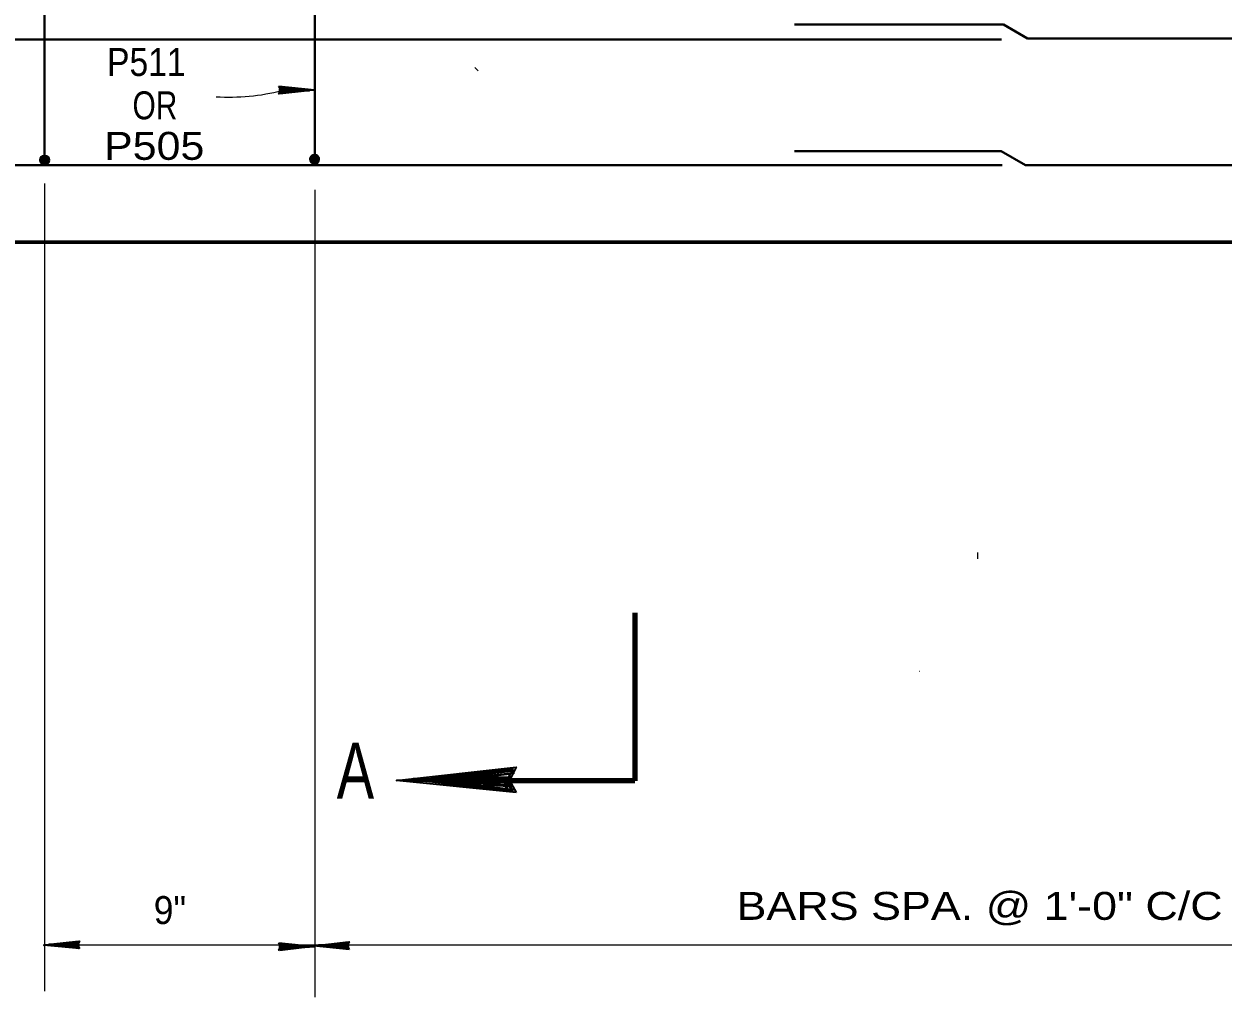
# Model space of a CAD drawing. Extents: x 6.34 to 9.53, y -1.46 to 0.53.
# Drawn here: x 6.7323 to 7.0899, y -1.0312 to -0.7412 of the extents above; entities that cross this region are included whole.
import ezdxf

# ---------------------------------------------------------------- set-up
doc = ezdxf.new("R2010")
doc.units = 0
doc.header["$LTSCALE"] = 0.0033
doc.layers.add('1', color=7, linetype='Continuous', lineweight=40)

msp = doc.modelspace()

# ---------------------------------------------------------------- linework, layer by layer
at = {"layer": '1'}
for p, q in [((6.738417, -0.6685), (6.738417, -0.780333)), ((6.819083, -0.667833), (6.819083, -0.780833)), ((6.737833, -0.780583), (6.7375, -0.782583)), ((6.737917, -0.780667), (6.737583, -0.782583)), ((6.738, -0.780667), (6.737667, -0.782583)), ((6.739167, -0.782), (6.737667, -0.781833)), ((6.739167, -0.782167), (6.737667, -0.782)), ((6.739167, -0.78225), (6.737667, -0.782167)), ((6.739167, -0.78225), (6.737667, -0.782167)), ((6.739167, -0.782333), (6.737667, -0.78225)), ((6.739167, -0.782417), (6.737667, -0.782333)), ((6.739167, -0.7825), (6.737667, -0.782417)), ((6.739167, -0.782583), (6.737667, -0.7825)), ((6.739167, -0.782667), (6.737667, -0.782583)), ((6.739167, -0.78275), (6.737667, -0.782667)), ((6.739167, -0.782917), (6.737667, -0.782833)), ((6.738083, -0.780667), (6.73775, -0.782667)), ((6.73925, -0.780833), (6.73775, -0.78075)), ((6.73925, -0.780917), (6.73775, -0.780833)), ((6.73925, -0.781), (6.73775, -0.780917)), ((6.73925, -0.781083), (6.73775, -0.781)), ((6.73925, -0.781167), (6.73775, -0.781083)), ((6.73925, -0.781333), (6.73775, -0.78125)), ((6.73925, -0.781417), (6.73775, -0.781333)), ((6.73925, -0.7815), (6.73775, -0.781417)), ((6.73925, -0.781583), (6.73775, -0.7815)), ((6.73925, -0.781667), (6.73775, -0.781583)), ((6.73925, -0.78175), (6.73775, -0.781667)), ((6.73925, -0.781833), (6.73775, -0.78175)), ((6.738333, -0.780667), (6.737917, -0.782667)), ((6.7385, -0.78075), (6.738083, -0.782667)), ((6.738583, -0.78075), (6.738167, -0.782667)), ((6.738667, -0.78075), (6.73825, -0.78275)), ((6.73875, -0.78075), (6.738417, -0.78275)), ((6.738833, -0.780833), (6.7385, -0.78275)), ((6.739, -0.780833), (6.738583, -0.782833)), ((6.739083, -0.780833), (6.738667, -0.782833)), ((6.739167, -0.780833), (6.738833, -0.782833)), ((6.73925, -0.780833), (6.738917, -0.782833)), ((6.739417, -0.780917), (6.739083, -0.782833)), ((6.818333, -0.780333), (6.818, -0.782333)), ((6.818417, -0.780417), (6.818083, -0.782333)), ((6.8185, -0.780417), (6.818167, -0.782333)), ((6.819667, -0.78175), (6.818167, -0.781583)), ((6.819667, -0.781917), (6.818167, -0.78175)), ((6.819667, -0.782), (6.818167, -0.781917)), ((6.819667, -0.782), (6.818167, -0.781917)), ((6.819667, -0.782083), (6.818167, -0.782)), ((6.819667, -0.782167), (6.818167, -0.782083)), ((6.819667, -0.78225), (6.818167, -0.782167)), ((6.819667, -0.782333), (6.818167, -0.78225)), ((6.819667, -0.782417), (6.818167, -0.782333)), ((6.819667, -0.7825), (6.818167, -0.782417)), ((6.819667, -0.782667), (6.818167, -0.782583)), ((6.818583, -0.780417), (6.81825, -0.782417)), ((6.81975, -0.780583), (6.81825, -0.7805)), ((6.81975, -0.780667), (6.81825, -0.780583)), ((6.81975, -0.78075), (6.81825, -0.780667)), ((6.81975, -0.780833), (6.81825, -0.78075)), ((6.81975, -0.780917), (6.81825, -0.780833)), ((6.81975, -0.781083), (6.81825, -0.781)), ((6.81975, -0.781167), (6.81825, -0.781083)), ((6.81975, -0.78125), (6.81825, -0.781167)), ((6.81975, -0.781333), (6.81825, -0.78125)), ((6.81975, -0.781417), (6.81825, -0.781333)), ((6.81975, -0.7815), (6.81825, -0.781417)), ((6.81975, -0.781583), (6.81825, -0.7815)), ((6.818833, -0.780417), (6.818417, -0.782417)), ((6.819, -0.7805), (6.818583, -0.782417)), ((6.819083, -0.7805), (6.818667, -0.782417)), ((6.819167, -0.7805), (6.81875, -0.7825)), ((6.81925, -0.7805), (6.818917, -0.7825)), ((6.819333, -0.780583), (6.819, -0.7825)), ((6.8195, -0.780583), (6.819083, -0.782583)), ((6.819583, -0.780583), (6.819167, -0.782583)), ((6.819667, -0.780583), (6.819333, -0.782583)), ((6.81975, -0.780583), (6.819417, -0.782583)), ((6.819917, -0.780667), (6.819583, -0.782583))]:
    msp.add_line(p, q, dxfattribs=at)
at = {"layer": '1', "lineweight": 25}
for p, q in [((6.86675, -0.754167), (6.86775, -0.755167)), ((6.999333, -0.934083), (6.999417, -0.934083)), ((6.999333, -0.934083), (6.999417, -0.934083))]:
    msp.add_line(p, q, dxfattribs=at)
at = {"layer": '1', "lineweight": 35}
for p, q in [((6.808333, -0.760833), (6.818917, -0.760833)), ((6.8085, -0.7615), (6.815833, -0.76075)), ((6.808583, -0.759833), (6.816417, -0.76075)), ((6.808583, -0.759833), (6.816417, -0.76075)), ((6.808583, -0.759917), (6.816417, -0.76075)), ((6.808583, -0.76), (6.816417, -0.760833)), ((6.808583, -0.76), (6.816417, -0.761)), ((6.808583, -0.761667), (6.815917, -0.760833)), ((6.808583, -0.76175), (6.815917, -0.761)), ((6.808583, -0.761917), (6.815917, -0.761083)), ((6.878333, -0.963), (6.853583, -0.96575)), ((6.878333, -0.9635), (6.853583, -0.966167)), ((6.878333, -0.963917), (6.853583, -0.96675)), ((6.878583, -0.9645), (6.853667, -0.966917)), ((6.879083, -0.96675), (6.843417, -0.96675)), ((6.878333, -0.9695), (6.85175, -0.966167)), ((6.878333, -0.9695), (6.85175, -0.96675)), ((6.878333, -0.970167), (6.85175, -0.966917)), ((6.878333, -0.970167), (6.85175, -0.966917)), ((6.878333, -0.96975), (6.85175, -0.966917)), ((6.748583, -1.016583), (6.74075, -1.015583)), ((6.748583, -1.014667), (6.74125, -1.0155)), ((6.748583, -1.014833), (6.74125, -1.015583)), ((6.748583, -1.014917), (6.74125, -1.01575)), ((6.748667, -1.015083), (6.741333, -1.015833)), ((6.808583, -1.015167), (6.816417, -1.016083)), ((6.808583, -1.015167), (6.816417, -1.016083)), ((6.808583, -1.01525), (6.816417, -1.016083)), ((6.808583, -1.015333), (6.816417, -1.016167)), ((6.808583, -1.015333), (6.816417, -1.016333)), ((6.829, -1.014917), (6.821667, -1.01575)), ((6.829, -1.015083), (6.821667, -1.015833)), ((6.829, -1.015167), (6.821667, -1.016)), ((6.829083, -1.015333), (6.82175, -1.016083)), ((6.748833, -1.01575), (6.73825, -1.01575)), ((6.748583, -1.016583), (6.74075, -1.01575)), ((6.748583, -1.01675), (6.74075, -1.015833)), ((6.748583, -1.01675), (6.74075, -1.015833)), ((6.748583, -1.016667), (6.74075, -1.015833)), ((6.808333, -1.016167), (6.818917, -1.016167)), ((6.8085, -1.016833), (6.815833, -1.016083)), ((6.808583, -1.017), (6.815917, -1.016167)), ((6.808583, -1.017083), (6.815917, -1.016333)), ((6.808583, -1.01725), (6.815917, -1.016417)), ((6.82925, -1.016), (6.818667, -1.016)), ((6.829, -1.016833), (6.821167, -1.015833)), ((6.829, -1.016833), (6.821167, -1.016)), ((6.829, -1.017), (6.821167, -1.016083)), ((6.829, -1.017), (6.821167, -1.016083)), ((6.829, -1.016917), (6.821167, -1.016083))]:
    msp.add_line(p, q, dxfattribs=at)
at = {"layer": '1', "lineweight": 13}
for p, q in [((6.738417, -0.780333), (6.738417, -0.780417)), ((6.738417, -0.78875), (6.738417, -1.0295)), ((6.819083, -0.790583), (6.819083, -1.03125)), ((7.01675, -0.89875), (7.01675, -0.900667)), ((7.01675, -0.89875), (7.01675, -0.900667)), ((7.290917, -1.01575), (6.739167, -1.01575))]:
    msp.add_line(p, q, dxfattribs=at)
at = {"layer": '1', "lineweight": 60}
msp.add_line((7.385583, -0.80625), (6.635583, -0.80625), dxfattribs=at)
at = {"layer": '1', "lineweight": 90}
for p, q in [((6.9145, -0.91675), (6.9145, -0.966833)), ((6.9145, -0.966833), (6.872833, -0.966833))]:
    msp.add_line(p, q, dxfattribs=at)
at = {"layer": '1'}
for points in [[(6.962083, -0.741333), (7.024417, -0.741333), (7.031667, -0.7455), (7.367083, -0.7455)], [(6.654, -0.745833), (6.962083, -0.745833), (7.023833, -0.745833)], [(6.962167, -0.779083), (7.02375, -0.779083), (7.031, -0.78325), (7.367917, -0.78325)], [(6.738417, -0.780417), (6.73875, -0.783), (6.73925, -0.780667), (6.738167, -0.783), (6.73775, -0.780583), (6.737417, -0.782583), (6.7395, -0.782583), (6.737167, -0.781667), (6.73975, -0.781917), (6.737417, -0.780917), (6.73975, -0.78125), (6.737167, -0.782083), (6.738917, -0.7805), (6.739083, -0.782917), (6.73725, -0.78125), (6.739667, -0.782333), (6.73925, -0.780667), (6.73775, -0.780583), (6.737167, -0.781667), (6.737417, -0.782583), (6.738167, -0.783), (6.739083, -0.782917), (6.739667, -0.782333), (6.738583, -0.781667), (6.737667, -0.782833), (6.737417, -0.780917), (6.738583, -0.781667), (6.739083, -0.780583), (6.73975, -0.781583), (6.738667, -0.781667), (6.737417, -0.7825), (6.738667, -0.7805), (6.739, -0.781833), (6.7395, -0.782583)], [(6.818917, -0.780167), (6.81925, -0.78275), (6.81975, -0.780417), (6.818667, -0.78275), (6.81825, -0.780333), (6.817917, -0.782333), (6.82, -0.782333), (6.817667, -0.781417), (6.82025, -0.781667), (6.817917, -0.780667), (6.82025, -0.781), (6.817667, -0.781833), (6.819417, -0.78025), (6.819583, -0.782667), (6.81775, -0.781), (6.820167, -0.782083), (6.81975, -0.780417), (6.81825, -0.780333), (6.817667, -0.781417), (6.817917, -0.782333), (6.818667, -0.78275), (6.819583, -0.782667), (6.820167, -0.782083), (6.819083, -0.781417), (6.818167, -0.782583), (6.817917, -0.780667), (6.819083, -0.781417), (6.819583, -0.780333), (6.82025, -0.781333), (6.819167, -0.781417), (6.817917, -0.78225), (6.819167, -0.78025), (6.8195, -0.781583), (6.82, -0.782333)], [(6.653167, -0.78325), (6.962167, -0.78325), (7.024083, -0.78325)]]:
    msp.add_lwpolyline(points, dxfattribs=at)
at = {"layer": '1', "lineweight": 35}
for points in [[(6.808333, -0.75975), (6.818917, -0.760833), (6.808333, -0.762), (6.808917, -0.760833)], [(6.809083, -0.76075), (6.81375, -0.760667), (6.81375, -0.76075), (6.812833, -0.76075), (6.809083, -0.760667), (6.812083, -0.760583), (6.808917, -0.7605), (6.811167, -0.760417), (6.808917, -0.760333), (6.812417, -0.760583), (6.817083, -0.76075), (6.816167, -0.761), (6.817417, -0.761), (6.809083, -0.761), (6.8115, -0.761167), (6.808917, -0.761167), (6.81425, -0.76075), (6.808917, -0.761417)], [(6.879083, -0.97025), (6.843417, -0.96675), (6.879083, -0.96275), (6.877167, -0.96675)], [(6.876667, -0.966917), (6.860833, -0.96725), (6.860833, -0.966917), (6.863833, -0.966917), (6.876667, -0.96725), (6.866417, -0.9675), (6.877167, -0.967917), (6.869417, -0.968), (6.877167, -0.968417), (6.865333, -0.9675), (6.8495, -0.966917), (6.852583, -0.966167), (6.848417, -0.966167), (6.876667, -0.966167), (6.868333, -0.965667), (6.877167, -0.965667), (6.859167, -0.966917), (6.877167, -0.964667)], [(6.748833, -1.016833), (6.73825, -1.01575), (6.748833, -1.014583), (6.74825, -1.01575)], [(6.748083, -1.015833), (6.743417, -1.015917), (6.743417, -1.015833), (6.744333, -1.015833), (6.748083, -1.015917), (6.745083, -1.016), (6.74825, -1.016083), (6.746, -1.016167), (6.74825, -1.01625), (6.74475, -1.016), (6.740083, -1.015833), (6.741, -1.015583), (6.73975, -1.015583), (6.748083, -1.015583), (6.745667, -1.015417), (6.74825, -1.015417), (6.742917, -1.015833), (6.74825, -1.015167)], [(6.808333, -1.015083), (6.818917, -1.016167), (6.808333, -1.017333), (6.808917, -1.016167)], [(6.809083, -1.016083), (6.81375, -1.016), (6.81375, -1.016083), (6.812833, -1.016083), (6.809083, -1.016), (6.812083, -1.015917), (6.808917, -1.015833), (6.811167, -1.01575), (6.808917, -1.015667), (6.812417, -1.015917), (6.817083, -1.016083), (6.816167, -1.016333), (6.817417, -1.016333), (6.809083, -1.016333), (6.8115, -1.0165), (6.808917, -1.0165), (6.81425, -1.016083), (6.808917, -1.01675)], [(6.82925, -1.017083), (6.818667, -1.016), (6.82925, -1.014833), (6.828667, -1.016)], [(6.8285, -1.016083), (6.823833, -1.016167), (6.823833, -1.016083), (6.82475, -1.016083), (6.8285, -1.016167), (6.8255, -1.01625), (6.828667, -1.016333), (6.826417, -1.016417), (6.828667, -1.0165), (6.825167, -1.01625), (6.8205, -1.016083), (6.821417, -1.015833), (6.820167, -1.015833), (6.8285, -1.015833), (6.826083, -1.015667), (6.828667, -1.015667), (6.823333, -1.016083), (6.828667, -1.015417)]]:
    msp.add_lwpolyline(points, close=True, dxfattribs=at)
for points in [[(6.809083, -0.76075), (6.808667, -0.76), (6.808917, -0.76025), (6.809083, -0.760583), (6.809333, -0.7605), (6.809167, -0.760167), (6.809, -0.760917), (6.808833, -0.761417), (6.808583, -0.761833)], [(6.876667, -0.966917), (6.877917, -0.9695), (6.877167, -0.968667), (6.876667, -0.9675), (6.875667, -0.967917), (6.876333, -0.969), (6.876833, -0.966417), (6.877417, -0.964667), (6.878333, -0.963417)], [(6.748083, -1.015833), (6.7485, -1.016583), (6.74825, -1.016333), (6.748083, -1.016), (6.747833, -1.016083), (6.748, -1.016417), (6.748167, -1.015667), (6.748333, -1.015167), (6.748583, -1.01475)], [(6.809083, -1.016083), (6.808667, -1.015333), (6.808917, -1.015583), (6.809083, -1.015917), (6.809333, -1.015833), (6.809167, -1.0155), (6.809, -1.01625), (6.808833, -1.01675), (6.808583, -1.017167)], [(6.8285, -1.016083), (6.828917, -1.016833), (6.828667, -1.016583), (6.8285, -1.01625), (6.82825, -1.016333), (6.828417, -1.016667), (6.828583, -1.015917), (6.82875, -1.015417), (6.829, -1.015)]]:
    msp.add_lwpolyline(points, dxfattribs=at)
at = {"layer": '1'}
for centre in [(6.738467, -0.78175), (6.818967, -0.7815)]:
    msp.add_circle(centre, 0.00132, dxfattribs=at)
at = {"layer": '1', "lineweight": 13}
msp.add_arc((6.793625, -0.699788), 0.063175, 266.33195, 284.31953, dxfattribs=at)

# ---------------------------------------------------------------- texts
at = {"layer": '1'}
for s, height, width, p in [('P511', 0.008334, 0.9, (6.757083, -0.756667)), ('OR', 0.008334, 0.8, (6.764667, -0.769583)), ('P505', 0.008334, 1.15, (6.756167, -0.781667)), ('A', 0.01667, 0.75, (6.825583, -0.972083)), ('9"', 0.008334, 0.95, (6.771, -1.0095)), ('BARS SPA. @ 1\'-0" C/C', 0.008334, 1.2, (6.944833, -1.00825))]:
    msp.add_text(s, height=height, dxfattribs=dict(at, width=width)).set_placement(p)

doc.saveas('drawing.dxf')
